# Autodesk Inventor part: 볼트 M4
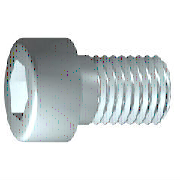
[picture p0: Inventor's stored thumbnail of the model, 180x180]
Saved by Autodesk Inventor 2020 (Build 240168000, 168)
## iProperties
IsCustomPart: 0
Created: 2012-02
Part Number: 볼트 M4
Material: 스테인리스강
Description: 6각 소켓 머리 캡 나사
Document SubType Name: Modeling
Standard: ISO 4762
Designer: mduedu
Standard Revision: Fourth edition 2004-03-01
Standards Organization: ISO
Language: ko-KR
Size Designation: M4 x 12
Categories: <MemberInstance><Categories><Category DisplayName="조임쇠" InternalName="e4da775c-781d-43d5-af7c-5136215cf5a6" Mnemonic="FSTN"><Category DisplayName="볼트" InternalN
Density: 8.08 g/cm^3
Appearance: 반광택
Author: mduedu
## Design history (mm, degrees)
sketch "스케치1"
  geometry: L1 (-1, 0)-(12, 0); L2 (12, 0)-(12, 2); L3 (12, 2)-(1.75, 2); L4 (1.75, 2)-(1.32, 2); L5 (1.32, 2)-(0, 2); L6 (0, 2)-(0, 3.5); L7 (0, 3.5)-(-4, 3.5); L8 (-4, 3.5)-(-4, 1.732); L9 (-4, 1.732)-(-2, 1.732); L10 (-2, 1.732)-(-1, 0); L11 (-7.2, 0)-(15.2, 0) reference; L12 (0, -0.7)-(0, 4.2) reference; L13 (1.75, 2)-(0, 2)
  constraints: 22 end point, 6 parallel, 2 collinear, 2 perpendicular, 1 horizontal, 1 point on line
  dimensions: "d1" = 10.25 distance from line of L3.end L2 (= GEL); "d2" = 0.42952 distance of L4.end L3.end (computed from GAL); "d3" = 4 distance between parallel lines of L8 L6 (= KOH); "d4" = 2 distance of L8.end L9.end (= INTI); "d5" = 60 deg angle of L10 L1; "d6" = 4 diameter of L3 L1 (= GD); "d7" = 4 diameter of L5 L1 (= BDM); "d8" = 3.4641 diameter of L9 L1 (= 1.1547 x SW); "d9" = 7 diameter of L7 L1 (= KOD); "d26" = 12 distance between parallel lines of L12 L2 (= NLG)
revolve "본체" sketch "스케치1" stored, may be unused: angle "d10" = 90 deg
sketch "스케치2"
  geometry: L1 (0, -4.9)-(0, 4.9) reference; L2 (-4.9, 0)-(4.9, 0) reference; L3 (1.732, 0)-(0.866, -1.5); L4 (0.866, -1.5)-(-0.866, -1.5); L5 (-0.866, -1.5)-(-1.732, 0); L6 (-1.732, 0)-(-0.866, 1.5); L7 (-0.866, 1.5)-(0.866, 1.5); L8 (0.866, 1.5)-(1.732, 0); 2 further points
  constraints: 12 end point, 1 coincident, 1 horizontal alignment, 1 point on line, 12 other
extrude "슬롯" join sketch "스케치2" stored distance "d11" = 10; taper "d12" = 0 deg
workplane "Work Plane1"
fillet "Fillet2" dims "d30" = 0.1 (= R)
body "Solid1"
fillet "모깎기1" dims "d17" = 0.4 (= RR)
feature "스레드" dims "d13" = 10.25 (= GEL), "d14" = 0
chamfer "모따기1" distance "d15" = 0.42941 (= -0.5 x SPD + 0.5 x GD); stored, may be unused: second distance "d16" = 0.42941 (= GUL), angle "d27" = 45 deg
other parameters: "GD" = 4 [user parameter; used in 2 equation terms], "NLG" = 12 [user parameter; used in 1 equation term], "GEL" = 10.25 [user parameter; used in 2 equation terms], "KOD" = 7 [user parameter; used in 1 equation term], "KOH" = 4 [user parameter; used in 1 equation term], "INTI" = 2 [user parameter; used in 1 equation term], "GAL" = 0.42941 (= 0.61345 x PTC) [user parameter; used in 1 equation term], "GUL" = 0.42941 (= 0.61345 x PTC) [user parameter; used in 1 equation term], "BDM" = 4 (= NND) [user parameter; used in 1 equation term], "SW" = 3 [user parameter; used in 2 equation terms], "RR" = 0.4 [user parameter; used in 1 equation term], "SPD" = 3.14117 (= NND - 1.2269 x PTC) [user parameter; used in 1 equation term], "d19" = 0, "d28" = 0, "d29" = 0, "R" = 0.1 [user parameter; used in 1 equation term], "TOA" = 30 deg [user parameter], "GD1" = 3.14117 (= THREADDIA - 1.2269 x PTC) [user parameter], "THREADDIA" = 4 [user parameter; used in 1 equation term], "FAWI" = 45 deg [user parameter], "TPU" = 14.28571 (computed from PTC) [user parameter], "PTC" = 0.7 [user parameter; used in 5 equation terms], "NND" = 4 [user parameter; used in 2 equation terms], "E0" = 3.465 (= 1.155 x SW) [user parameter]
